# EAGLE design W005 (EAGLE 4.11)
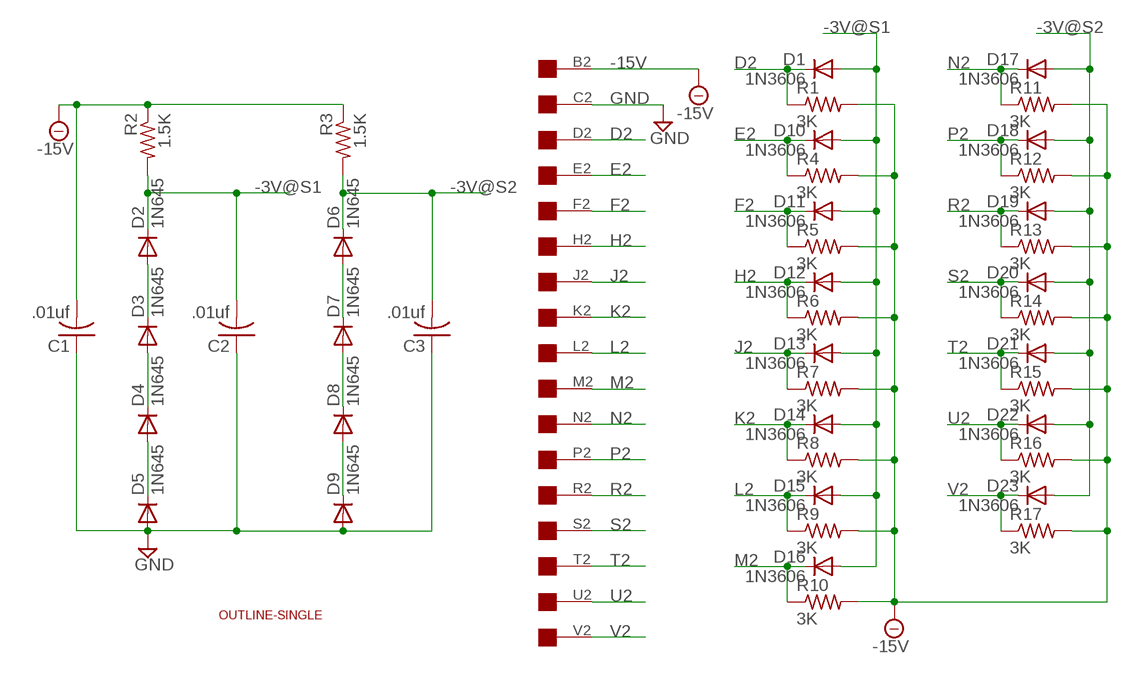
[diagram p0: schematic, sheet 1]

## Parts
C1  .01uf  C-US050-025X075  [C050-025X075]
C2  .01uf  C-US050-025X075  [C050-025X075]
C3  .01uf  C-US050-025X075  [C050-025X075]
D1  1N3606  1N4148  [DO35-10]
D2  1N645  1N4148  [DO35-10]
D3  1N645  1N4148  [DO35-10]
D4  1N645  1N4148  [DO35-10]
D5  1N645  1N4148  [DO35-10]
D6  1N645  1N4148  [DO35-10]
D7  1N645  1N4148  [DO35-10]
D8  1N645  1N4148  [DO35-10]
D9  1N645  1N4148  [DO35-10]
D10  1N3606  1N4148  [DO35-10]
D11  1N3606  1N4148  [DO35-10]
D12  1N3606  1N4148  [DO35-10]
D13  1N3606  1N4148  [DO35-10]
D14  1N3606  1N4148  [DO35-10]
D15  1N3606  1N4148  [DO35-10]
D16  1N3606  1N4148  [DO35-10]
D17  1N3606  1N4148  [DO35-10]
D18  1N3606  1N4148  [DO35-10]
D19  1N3606  1N4148  [DO35-10]
D20  1N3606  1N4148  [DO35-10]
D21  1N3606  1N4148  [DO35-10]
D22  1N3606  1N4148  [DO35-10]
D23  1N3606  1N4148  [DO35-10]
R1  3K  R-US_0207/10  [0207/10]
R2  1.5K  R-US_0207/10  [0207/10]
R3  1.5K  R-US_0207/10  [0207/10]
R4  3K  R-US_0207/10  [0207/10]
R5  3K  R-US_0207/10  [0207/10]
R6  3K  R-US_0207/10  [0207/10]
R7  3K  R-US_0207/10  [0207/10]
R8  3K  R-US_0207/10  [0207/10]
R9  3K  R-US_0207/10  [0207/10]
R10  3K  R-US_0207/10  [0207/10]
R11  3K  R-US_0207/10  [0207/10]
R12  3K  R-US_0207/10  [0207/10]
R13  3K  R-US_0207/10  [0207/10]
R14  3K  R-US_0207/10  [0207/10]
R15  3K  R-US_0207/10  [0207/10]
R16  3K  R-US_0207/10  [0207/10]
R17  3K  R-US_0207/10  [0207/10]
U$1  EDGE-1  [EDGE-CON1]
U$2  OUTLINE-SINGLE  [SINGLE]

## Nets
-3V@S1: C2.2 D1.A D2.C D10.A D11.A D12.A D13.A D14.A D15.A D16.A R2.2
-3V@S2: C3.2 D6.C D17.A D18.A D19.A D20.A D21.A D22.A D23.A R3.2
-15V: C1.2 R1.2 R2.1 R3.1 R4.2 R5.2 R6.2 R7.2 R8.2 R9.2 R10.2 R11.2 R12.2 R13.2 R14.2 R15.2 R16.2 R17.2 U$1.B2
D2: D1.C R1.1 U$1.D2
E2: D10.C R4.1 U$1.E2
F2: D11.C R5.1 U$1.F2
GND: C1.1 C2.1 C3.1 D5.A D9.A U$1.C2
H2: D12.C R6.1 U$1.H2
J2: D13.C R7.1 U$1.J2
K2: D14.C R8.1 U$1.K2
L2: D15.C R9.1 U$1.L2
M2: D16.C R10.1 U$1.M2
N2: D17.C R11.1 U$1.N2
N$2: D2.A D3.C
N$3: D3.A D4.C
N$4: D4.A D5.C
N$7: D8.A D9.C
N$8: D7.A D8.C
N$9: D6.A D7.C
P2: D18.C R12.1 U$1.P2
R2: D19.C R13.1 U$1.R2
S2: D20.C R14.1 U$1.S2
T2: D21.C R15.1 U$1.T2
U2: D22.C R16.1 U$1.U2
V2: D23.C R17.1 U$1.V2
Unconnected: U$1.A2

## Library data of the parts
C1-C3 = rcl:C-US: CAPACITOR, American symbol
D1-D23 = diode:1N4148: DIODE
R1-R17 = rcl:R-US_: RESISTOR, American symbol
U$1 = dec-con:EDGE-1: Single-Sided DEC Edge Connector -- (side 2)
U$2 = dec-con:OUTLINE-*: Board outlines for DEC boards.

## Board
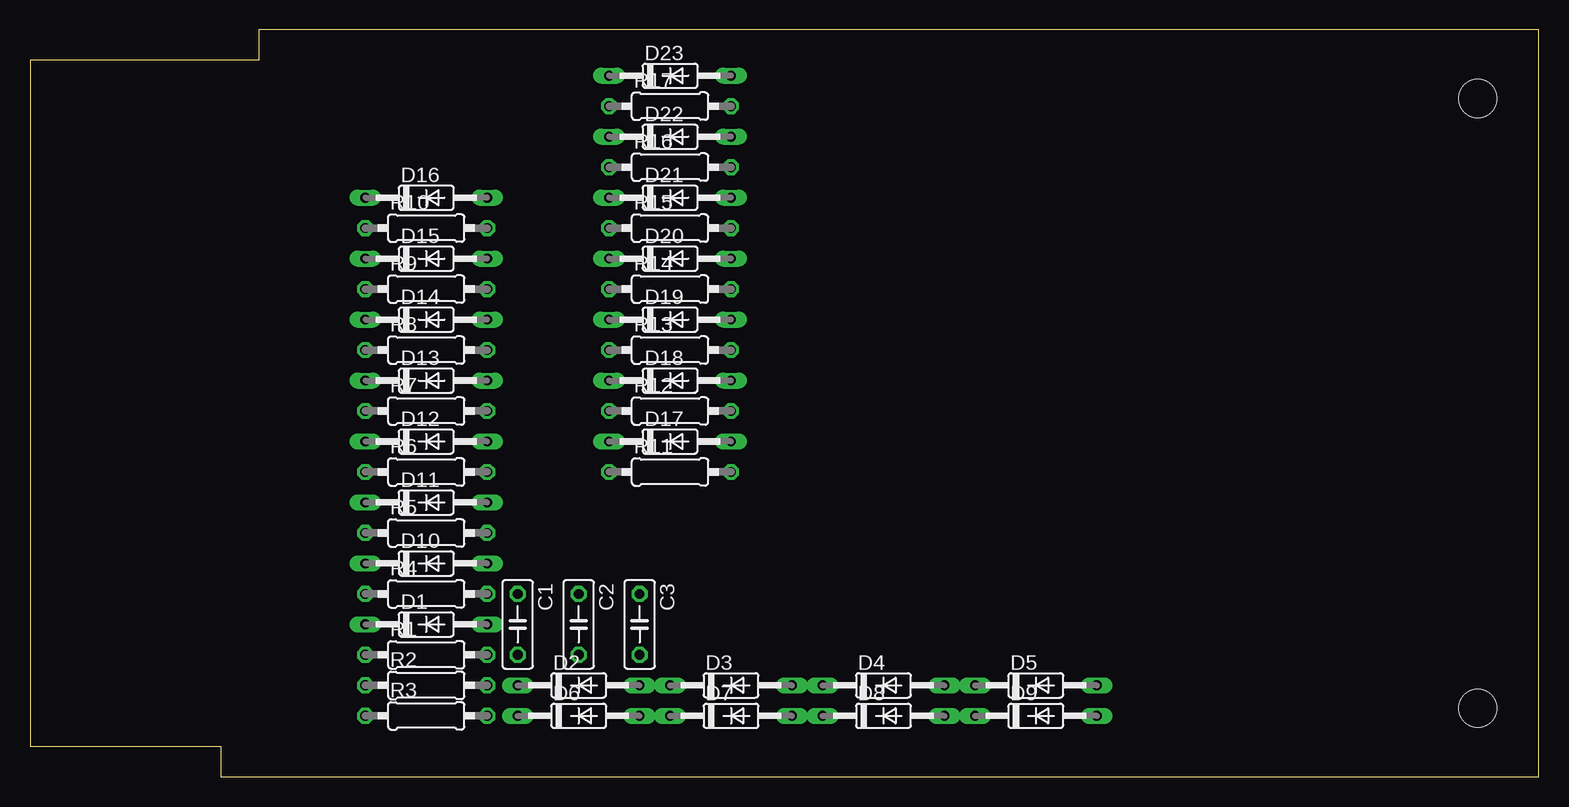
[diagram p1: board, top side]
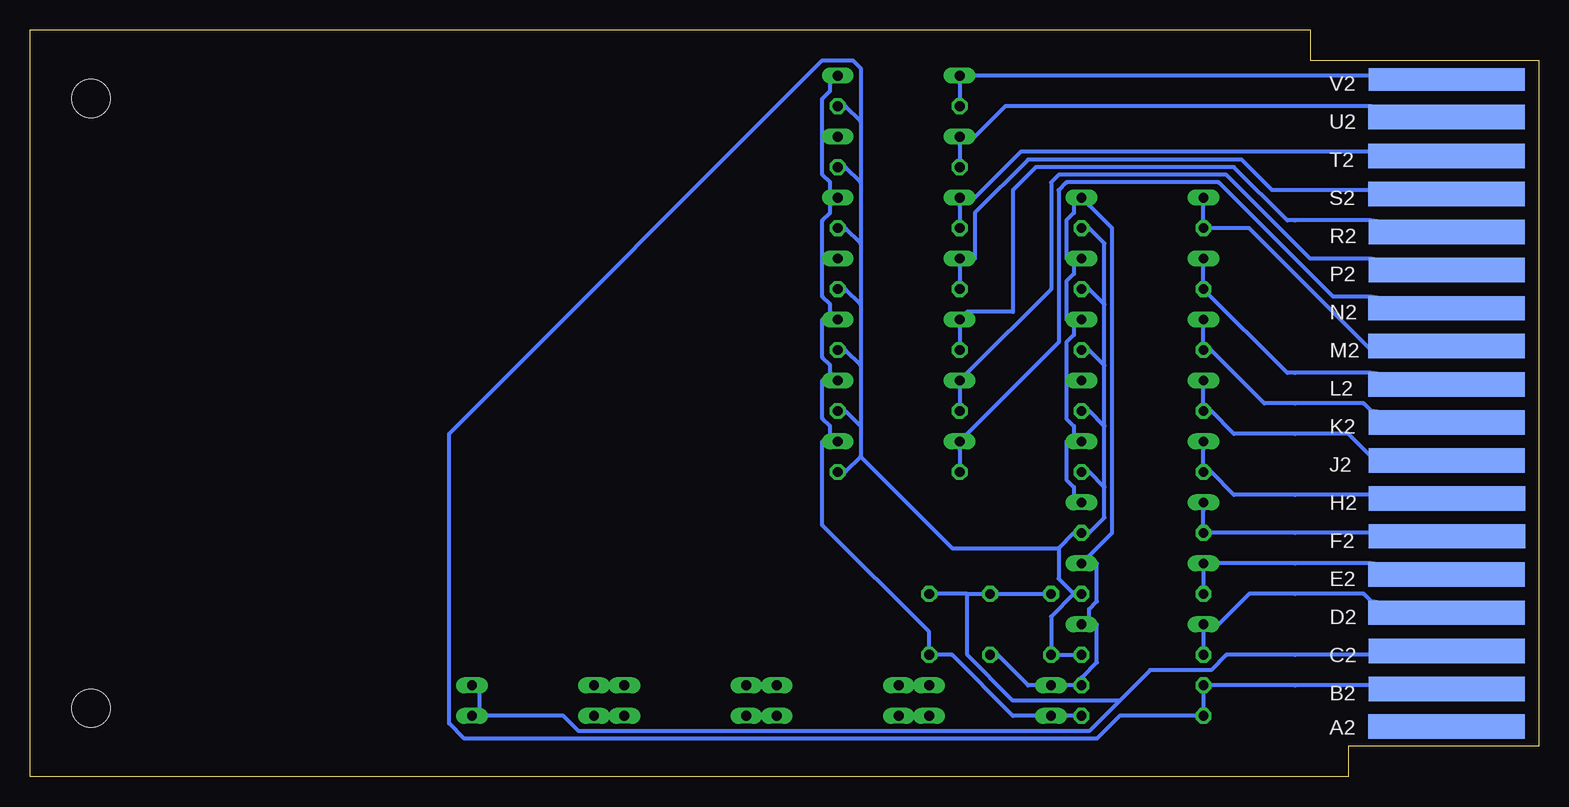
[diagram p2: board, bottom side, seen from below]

Size 125.73 x 62.23 mm. Coordinates in mm from the lower left corner, seen from the top.
Copper layers (1*16): Top 0.035mm / dielectric 1.5mm / Bottom 0.035mm
Design rules "10mils": minimum track width 13mil, minimum drill 28mil, track to track 10mil, track to pad 10mil, pad to pad 10mil, via to via 10mil, smd to smd 10mil, copper to edge 25mil, drill to drill 10mil, minimum pad ring 10mil, minimum via ring 8mil, stop-mask expansion 0mil, vias tented up to drill 0mil, thermal gap 10mil

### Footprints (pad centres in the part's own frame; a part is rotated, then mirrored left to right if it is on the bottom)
C050-025X075 = drill 0.813 octagon: 1 -2.54,0; 2 2.54,0
DO35-10 = drill 0.813 long: A 5.08,0; C -5.08,0
0207/10 = drill 0.813 octagon: 1 -5.08,0; 2 5.08,0
EDGE-CON1 = smd 13.017 x 2.032 bottom: A2 7.69,4.194; B2 7.668,7.328; C2 7.668,10.49; D2 7.693,13.665; E2 7.693,16.84; F2 7.642,20.041; H2 7.642,23.19; J2 7.668,26.34; K2 7.668,29.515; L2 7.693,32.69; M2 7.693,35.89; N2 7.693,39.04; P2 7.668,42.24; R2 7.668,45.39; S2 7.693,48.565; T2 7.693,51.74; U2 7.693,54.966 | smd 13.017 x 1.905 bottom: V2 7.668,58.102
SINGLE = hole 3.175: 120.65,56.515; 120.65,5.715

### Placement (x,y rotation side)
C1  40.64,12.7 270 top
C2  45.72,12.7 270 top
C3  50.8,12.7 270 top
D1  33.02,12.7 0 top
D2  45.72,7.62 0 top
D3  58.42,7.62 0 top
D4  71.12,7.62 0 top
D5  83.82,7.62 0 top
D6  45.72,5.08 0 top
D7  58.42,5.08 0 top
D8  71.12,5.08 0 top
D9  83.82,5.08 0 top
D10  33.02,17.78 0 top
D11  33.02,22.86 0 top
D12  33.02,27.94 0 top
D13  33.02,33.02 0 top
D14  33.02,38.1 0 top
D15  33.02,43.18 0 top
D16  33.02,48.26 0 top
D17  53.34,27.94 0 top
D18  53.34,33.02 0 top
D19  53.34,38.1 0 top
D20  53.34,43.18 0 top
D21  53.34,48.26 0 top
D22  53.34,53.34 0 top
D23  53.34,58.42 0 top
R1  33.02,10.16 0 top
R2  33.02,7.62 0 top
R3  33.02,5.08 0 top
R4  33.02,15.24 0 top
R5  33.02,20.32 0 top
R6  33.02,25.4 0 top
R7  33.02,30.48 0 top
R8  33.02,35.56 0 top
R9  33.02,40.64 0 top
R10  33.02,45.72 0 top
R11  53.34,25.4 0 top
R12  53.34,30.48 0 top
R13  53.34,35.56 0 top
R14  53.34,40.64 0 top
R15  53.34,45.72 0 top
R16  53.34,50.8 0 top
R17  53.34,55.88 0 top
U$1  0,0 0 top
U$2  0,0 0 top

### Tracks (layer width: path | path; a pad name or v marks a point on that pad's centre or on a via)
-3V@S1
  Bottom 0.33: C2.2 45.09,10.16 42.55,7.62 41.91,7.62 D2.C 39.37,7.62 38.74,7.62 R2.2 38.1,8.26 36.83,9.53 36.83,12.7 D1.A 37.47,13.34 37.47,13.97 36.83,14.61 36.83,17.78 D10.A 37.47,18.41 35.56,20.32 35.56,45.72 37.47,47.62 D16.A 38.74,47.62 38.74,46.99 39.37,46.35 39.37,43.18 D15.A 38.74,42.55 38.74,41.91 39.37,41.27 39.37,38.1 D14.A 38.74,37.47 38.74,36.83 39.37,36.2 39.37,33.02 | 39.37,33.02 D13.A 39.37,33.02 | D11.A 38.74,23.5 38.74,24.13 39.37,24.77 39.37,27.94 D12.A 38.74,28.57 38.74,29.21 39.37,29.84 39.37,33.02
-3V@S2
  Bottom 0.33: R3.2 38.74,5.08 39.37,5.08 D6.C 41.91,5.08 43.82,5.08 48.9,10.16 50.17,10.16 C3.2 50.8,10.79 50.8,12.06 59.69,20.95 59.69,27.94 D17.A 59.06,28.57 59.06,29.21 59.69,29.84 59.69,33.02 D18.A 59.06,33.66 59.06,34.29 59.69,34.92 59.69,38.1 D19.A 59.06,38.73 59.06,39.37 59.69,40.01 59.69,43.18 | 59.69,53.34 59.69,50.16 59.06,49.53 59.06,48.9 D21.A 59.06,47.62 59.06,46.99 59.69,46.35 59.69,43.18 | 59.69,53.34 D22.A 59.69,53.34 | 59.69,53.34 59.69,56.52 59.06,57.15 59.06,57.78 D23.A | 59.69,43.18 D20.A 59.69,43.18
-15V
  Bottom 0.33: R1.2 38.74,10.16 40.01,10.16 C1.2 40.64,10.79 40.64,13.34 38.74,15.24 | 38.74,15.24 R4.2 38.74,15.24 | 36.2,24.13 36.2,21.59 37.47,20.32 R5.2 38.74,20.32 40.01,19.05 | 36.2,24.13 37.47,25.4 R6.2 | 36.2,29.21 37.47,30.48 R7.2 | 36.2,24.13 36.2,29.21 | 36.2,34.29 37.47,35.56 R8.2 | 36.2,29.21 36.2,34.29 | 36.2,39.37 37.47,40.64 R9.2 | 36.2,34.29 36.2,39.37 | 36.2,39.37 36.2,44.45 37.47,45.72 R10.2 | 38.74,15.24 40.01,16.51 40.01,19.05 | 56.52,26.67 57.79,25.4 R11.2 | 56.52,29.21 56.52,26.67 | 56.52,29.21 57.79,30.48 R12.2 | 56.52,34.29 57.79,35.56 R13.2 | 56.52,34.29 56.52,29.21 | 56.52,39.37 57.79,40.64 R14.2 | 56.52,39.37 56.52,34.29 | 56.52,44.45 57.79,45.72 R15.2 | 56.52,44.45 56.52,39.37 | 56.52,49.53 57.79,50.8 R16.2 | 56.52,49.53 56.52,44.45 | 56.52,54.61 57.79,55.88 R17.2 | 56.52,54.61 56.52,49.53 | 56.52,54.61 56.52,59.05 57.15,59.69 59.69,59.69 90.81,28.57 90.81,4.45 89.54,3.17 36.83,3.17 34.93,5.08 28.58,5.08 R3.1 27.94,5.71 27.94,6.99 R2.1 27.31,7.62 20.32,7.62 13.97,7.62 U$1.B2 | 40.01,19.05 48.9,19.05 56.52,26.67
D2
  Bottom 0.33: R1.1 27.94,10.79 27.94,12.06 D1.C 26.67,12.7 24.13,15.24 20.32,15.24 14.61,15.24 13.97,14.61 U$1.D2
E2
  Bottom 0.33: R4.1 27.94,15.88 27.94,17.14 D10.C 26.67,17.78 20.32,17.78 13.97,17.78 U$1.E2
F2
  Bottom 0.33: D11.C 27.94,22.23 27.94,20.95 R5.1 27.31,20.32 20.32,20.32 13.97,20.32 U$1.F2
GND
  Bottom 0.33: D5.A 88.27,6.99 88.27,5.71 D9.A 87.63,5.08 81.28,5.08 80.01,3.81 37.47,3.81 34.93,6.35 | C1.1 41.28,15.24 45.09,15.24 C2.1 46.36,15.24 47.63,15.24 | 47.63,15.24 50.17,15.24 C3.1 | 34.93,6.35 32.39,8.89 27.31,8.89 26.04,10.16 20.32,10.16 13.97,10.16 U$1.C2 | 47.63,15.24 47.63,10.16 43.82,6.35 34.93,6.35
H2
  Bottom 0.33: D12.C 27.94,27.3 27.94,26.04 R6.1 27.31,25.4 25.4,23.5 20.32,23.5 13.97,23.5 U$1.H2
J2
  Bottom 0.33: D13.C 27.94,32.38 27.94,31.11 R7.1 27.31,30.48 25.4,28.57 20.32,28.57 15.88,28.57 13.97,26.67 U$1.J2
K2
  Bottom 0.33: D14.C 27.94,37.47 27.94,36.2 R8.1 27.31,35.56 22.86,31.11 20.32,31.11 14.61,31.11 13.97,30.48 U$1.K2
L2
  Bottom 0.33: D15.C 27.94,42.55 27.94,41.27 R9.1 20.96,33.66 20.32,33.66 13.97,33.66 U$1.L2
M2
  Bottom 0.33: D16.C 27.94,47.62 27.94,46.35 R10.1 27.31,45.72 24.13,45.72 13.97,35.56 U$1.M2
N2
  Bottom 0.33: R11.1 48.26,26.04 48.26,27.3 D17.C 47.63,28.57 40.01,36.2 40.01,48.9 39.37,49.53 26.67,49.53 17.15,40.01 13.97,40.01 U$1.N2
N$2
  Bottom 0.33: D2.A 52.07,7.62 D3.C
N$3
  Bottom 0.33: D3.A 64.77,7.62 D4.C
N$4
  Bottom 0.33: D4.A 77.47,7.62 D5.C
N$7
  Bottom 0.33: D8.A 77.47,5.08 D9.C
N$8
  Bottom 0.33: D7.A 64.77,5.08 D8.C
N$9
  Bottom 0.33: D6.A 52.07,5.08 D7.C
P2
  Bottom 0.33: R12.1 48.26,31.11 48.26,32.38 D18.C 47.63,33.66 40.64,40.64 40.64,49.53 40.01,50.16 26.04,50.16 19.05,43.18 13.97,43.18 U$1.P2
R2
  Bottom 0.33: R13.1 48.26,36.2 48.26,37.47 D19.C 47.63,38.73 43.82,38.73 43.82,48.9 41.91,50.8 25.4,50.8 20.96,46.35 20.32,46.35 13.97,46.35 U$1.R2
S2
  Bottom 0.33: R14.1 48.26,41.27 48.26,42.55 D20.C 46.99,43.18 46.99,46.99 42.55,51.44 24.77,51.44 22.23,48.9 20.32,48.9 13.97,48.9 U$1.S2
T2
  Bottom 0.33: R15.1 48.26,46.35 48.26,47.62 D21.C 46.99,48.26 43.18,52.07 13.97,52.07 U$1.T2
U2
  Bottom 0.33: R16.1 48.26,51.44 48.26,52.7 D22.C 46.99,53.34 44.45,55.88 20.32,55.88 13.97,55.88 U$1.U2
V2
  Bottom 0.33: R17.1 48.26,56.52 48.26,57.78 D23.C 46.99,58.42 20.32,58.42 13.97,58.42 U$1.V2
